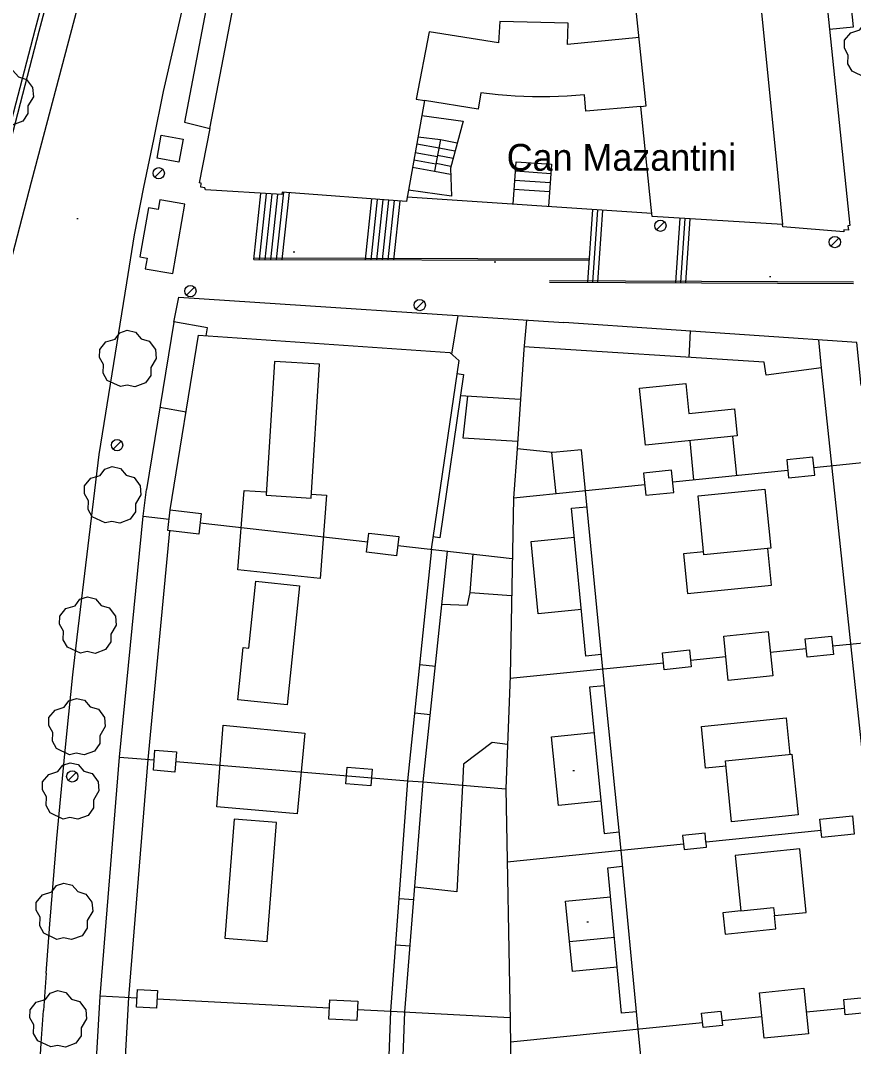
# Model space of a CAD drawing. Extents: x 431390 to 432653, y 4586754 to 4589600.
# Drawn here: x 431776 to 431835, y 4587093.8 to 4587166.5 of the extents above; entities that cross this region are included whole.
import ezdxf

# ---------------------------------------------------------------- set-up
doc = ezdxf.new("R2010")
doc.units = 0
for name, color, linetype in [('COM_16_LN', 7, 'Continuous'), ('COM_17LS_LN', 7, 'Continuous'), ('CON_01_LN', 7, 'Continuous'), ('CON_01FI_LN', 7, 'Continuous'), ('CON_03_LN', 7, 'Continuous'), ('CON_04_LN', 7, 'Continuous'), ('CON_07_LN', 7, 'Continuous'), ('CON_08_LN', 7, 'Continuous'), ('CON_14LN_LN', 7, 'Continuous'), ('CON_14LS_LN', 7, 'Continuous'), ('CON_15_LN', 7, 'Continuous'), ('CON_20_LN', 7, 'Continuous'), ('CON_23_LN', 7, 'Continuous'), ('ENE_06_PT', 7, 'Continuous'), ('ORO_03_PT', 7, 'Continuous'), ('TOP_06_TX', 7, 'Continuous'), ('VEG_03_PT', 7, 'Continuous')]:
    doc.layers.add(name, color=color, linetype=linetype)

msp = doc.modelspace()

# ---------------------------------------------------------------- linework, layer by layer
at = {"layer": 'COM_16_LN'}
msp.add_lwpolyline([(431779.803, 4587175.017), (431778.246, 4587170.313), (431777.035, 4587165.77), (431771.175, 4587143.287), (431765.02, 4587120.517), (431761.564, 4587107.321)], dxfattribs=at)
at = {"layer": 'COM_17LS_LN'}
for points in [[(431795.065, 4587216.598), (431793.497, 4587217.006), (431782.212, 4587174.845), (431780.492, 4587169.028), (431776.775, 4587155.017), (431774.643, 4587146.73), (431773.418, 4587141.925), (431772.51, 4587137.86), (431771.993, 4587135.123), (431771.464, 4587132.387), (431770.958, 4587129.648), (431770.51, 4587126.9), (431770.127, 4587124.069), (431769.799, 4587121.229), (431769.504, 4587118.385), (431769.22, 4587115.54), (431768.925, 4587112.483), (431768.651, 4587109.423), (431768.395, 4587106.362), (431768.15, 4587103.3), (431767.926, 4587100.444), (431767.711, 4587097.587), (431767.513, 4587094.729), (431767.34, 4587091.87)], [(431783.55, 4587147.89), (431784.109, 4587151.289), (431784.768, 4587154.673), (431785.467, 4587158.051), (431786.146, 4587161.432), (431788.285, 4587170.697), (431788.966, 4587173.068), (431792.266, 4587184.632), (431792.939, 4587186.992), (431800.194, 4587215.013), (431798.634, 4587215.414)], [(431780.05, 4587122.825), (431781.595, 4587135.739), (431783.55, 4587147.89)], [(431777.849, 4587099.039), (431778.119, 4587102.51), (431778.614, 4587108.56), (431778.882, 4587111.557), (431779.172, 4587114.563), (431779.453, 4587117.372), (431779.74, 4587120.139), (431780.05, 4587122.825)], [(431777.849, 4587099.039), (431777.652, 4587096.394)], [(431777.554, 4587046.85), (431777.386, 4587049.851), (431777.212, 4587052.828), (431777.056, 4587055.74), (431776.934, 4587058.594), (431776.822, 4587062.83), (431776.77, 4587067.088), (431776.768, 4587071.367), (431776.809, 4587075.663), (431776.88, 4587079.593), (431776.987, 4587083.513), (431777.134, 4587087.422), (431777.325, 4587091.323), (431777.492, 4587094.081), (431777.652, 4587096.394)]]:
    msp.add_lwpolyline(points, dxfattribs=at)
at = {"layer": 'CON_01_LN'}
for points in [[(431833.298, 4587165.852), (431834.732, 4587151.951)], [(431789.431, 4587158.817), (431788.67, 4587154.98)], [(431789.12, 4587154.47), (431789.09, 4587154.61), (431788.79, 4587154.66), (431788.81, 4587154.95), (431788.67, 4587154.98)], [(431803.404, 4587153.958), (431803.349, 4587153.651), (431794.55, 4587154.321), (431794.52, 4587154.14), (431789.12, 4587154.47)], [(431834.732, 4587151.951), (431834.602, 4587151.937), (431834.634, 4587151.629), (431834.325, 4587151.654), (431834.313, 4587151.505), (431830, 4587151.85), (431829.982, 4587152.031), (431820.736, 4587152.597), (431820.715, 4587152.808)], [(431786.89, 4587145.11), (431787.25, 4587146.89), (431814.5, 4587145.08)], [(431786.89, 4587145.11), (431784.94, 4587133.28)], [(431835.534, 4587140.632), (431835.228, 4587143.678), (431814.5, 4587145.08)], [(431784.71, 4587131.38), (431784.94, 4587133.28)], [(431780.668, 4587080.436), (431781.667, 4587097.393), (431783.034, 4587114.323), (431784.71, 4587131.38)]]:
    msp.add_lwpolyline(points, dxfattribs=at)
at = {"layer": 'CON_01FI_LN'}
for points in [[(431789.431, 4587158.817), (431791.586, 4587170.003), (431793.582, 4587180.383)], [(431831.857, 4587179.822), (431833.298, 4587165.852)], [(431820.715, 4587152.808), (431820.672, 4587153.229), (431819.94, 4587160.38), (431816.05, 4587160.04), (431815.95, 4587161.21), (431815.34, 4587161.156), (431814.729, 4587161.113), (431814.118, 4587161.083), (431813.506, 4587161.064), (431812.893, 4587161.057), (431812.281, 4587161.062), (431811.669, 4587161.079), (431811.058, 4587161.108), (431810.447, 4587161.148), (431809.837, 4587161.2), (431809.228, 4587161.264), (431808.62, 4587161.34), (431808.42, 4587160.18), (431804.63, 4587160.8), (431803.492, 4587154.449), (431803.404, 4587153.958)]]:
    msp.add_lwpolyline(points, dxfattribs=at)
at = {"layer": 'CON_03_LN'}
for points in [[(431819.94, 4587160.38), (431820.327, 4587160.414), (431818.925, 4587173.762)], [(431811.852, 4587145.256), (431811.65, 4587143.17), (431811.18, 4587136.14), (431810.92, 4587132.65), (431810.7, 4587120.08), (431810.38, 4587112.09), (431810.7, 4587095.66), (431810.873, 4587081.525)], [(431836.08, 4587135.203), (431832.202, 4587134.809)], [(431830.354, 4587134.622), (431822.198, 4587133.794)], [(431820.219, 4587133.594), (431810.92, 4587132.65)], [(431784.71, 4587131.38), (431786.551, 4587131.169)], [(431788.75, 4587130.917), (431800.619, 4587129.558)], [(431802.734, 4587129.316), (431810.845, 4587128.387)], [(431837.396, 4587122.564), (431833.518, 4587122.175)], [(431825.969, 4587121.416), (431823.468, 4587121.165)], [(431831.653, 4587121.987), (431829.111, 4587121.732)], [(431821.55, 4587120.973), (431810.692, 4587119.882)], [(431783.035, 4587114.334), (431785.495, 4587114.132)], [(431787.026, 4587114.006), (431803.441, 4587112.659), (431804.535, 4587112.57), (431807.314, 4587112.342), (431810.38, 4587112.09)], [(431832.706, 4587109.136), (431824.566, 4587108.317)], [(431822.965, 4587108.156), (431810.481, 4587106.9)], [(431781.669, 4587097.42), (431784.279, 4587097.283)], [(431785.701, 4587097.209), (431797.888, 4587096.573)], [(431799.884, 4587096.468), (431802.257, 4587096.345), (431810.695, 4587095.904)], [(431828.513, 4587095.949), (431825.686, 4587095.665)], [(431834.368, 4587096.538), (431831.662, 4587096.266)], [(431824.311, 4587095.526), (431810.718, 4587094.158)]]:
    msp.add_lwpolyline(points, dxfattribs=at)
at = {"layer": 'CON_04_LN'}
for points in [[(431826.406, 4587187.796), (431826.757, 4587184.3), (431829.653, 4587155.438), (431829.982, 4587152.031)], [(431819.818, 4587165.263), (431814.75, 4587164.76), (431814.79, 4587166.27), (431809.96, 4587166.4), (431809.86, 4587164.89), (431804.95, 4587165.669), (431804.045, 4587160.896), (431804.63, 4587160.8)], [(431806.558, 4587142.844), (431807.002, 4587145.578)], [(431789.183, 4587144.152), (431789.28, 4587144.72), (431786.896, 4587145.138)], [(431786.626, 4587131.826), (431788.64, 4587144.19), (431806.43, 4587142.96), (431807.05, 4587142.4), (431805.1, 4587129.045)], [(431823.374, 4587142.615), (431823.451, 4587144.475)], [(431832.74, 4587141.87), (431832.55, 4587143.859)], [(431836.188, 4587109.486), (431832.74, 4587141.87), (431828.82, 4587141.36), (431828.67, 4587142.27), (431811.67, 4587143.378)], [(431794.012, 4587142.334), (431793.413, 4587132.858), (431796.6, 4587132.656), (431797.199, 4587142.132), (431794.012, 4587142.334)], [(431806.914, 4587141.472), (431807.396, 4587141.402), (431805.709, 4587129.858), (431805.229, 4587129.928)], [(431820.268, 4587136.399), (431819.857, 4587140.45), (431823.119, 4587140.781), (431823.336, 4587138.646), (431826.576, 4587138.975), (431826.77, 4587137.059), (431820.268, 4587136.399)], [(431811.413, 4587139.63), (431807.176, 4587139.895)], [(431811.214, 4587136.655), (431807.36, 4587136.9), (431807.686, 4587139.863)], [(431787.753, 4587138.746), (431785.896, 4587139.082)], [(431823.403, 4587136.717), (431823.684, 4587133.945)], [(431826.435, 4587137.025), (431826.716, 4587134.253)], [(431820.995, 4587082.523), (431819.753, 4587095.067), (431818.546, 4587107.711), (431817.247, 4587120.54), (431815.74, 4587136.08), (431813.71, 4587135.88), (431811.18, 4587136.14)], [(431813.949, 4587132.957), (431813.652, 4587135.886)], [(431832.255, 4587134.285), (431832.126, 4587135.559), (431830.278, 4587135.371), (431830.407, 4587134.097), (431832.255, 4587134.285)], [(431822.273, 4587133.059), (431822.112, 4587134.637), (431820.134, 4587134.436), (431820.294, 4587132.858), (431822.273, 4587133.059)], [(431796.617, 4587132.931), (431797.7, 4587132.87), (431797.24, 4587126.98), (431791.41, 4587127.58), (431791.87, 4587133.2), (431793.429, 4587133.112)], [(431829.14, 4587129.112), (431824.415, 4587128.636), (431823.994, 4587132.82), (431828.719, 4587133.296), (431829.14, 4587129.112)], [(431788.825, 4587131.574), (431788.658, 4587130.117), (431786.459, 4587130.369), (431786.626, 4587131.826), (431788.825, 4587131.574)], [(431817.145, 4587121.588), (431816.06, 4587121.483), (431815.046, 4587131.942), (431816.131, 4587132.047)], [(431786.588, 4587130.354), (431785.048, 4587114.169), (431783.677, 4587097.315), (431782.766, 4587080.929)], [(431800.691, 4587130.18), (431802.806, 4587129.937), (431802.65, 4587128.582), (431800.535, 4587128.825), (431800.691, 4587130.18)], [(431815.742, 4587124.766), (431812.685, 4587124.47), (431812.188, 4587129.599), (431815.244, 4587129.895)], [(431801.663, 4587080.616), (431802.257, 4587096.345), (431803.441, 4587112.659), (431805.155, 4587129.039)], [(431801.711, 4587081.887), (431802.699, 4587081.85), (431803.244, 4587096.293), (431804.535, 4587112.57), (431806.259, 4587128.912)], [(431807.86, 4587125.97), (431808.068, 4587128.705)], [(431824.393, 4587128.855), (431822.966, 4587128.712), (431823.248, 4587125.9), (431829.189, 4587126.496), (431828.929, 4587129.091)], [(431795.786, 4587126.455), (431794.899, 4587118.02), (431791.41, 4587118.387), (431791.8, 4587122.09), (431792.202, 4587122.048), (431792.7, 4587126.78), (431795.786, 4587126.455)], [(431805.863, 4587125.155), (431807.67, 4587125.09), (431807.86, 4587125.97), (431810.799, 4587125.76)], [(431826.136, 4587119.752), (431825.821, 4587122.89), (431828.963, 4587123.206), (431829.278, 4587120.068), (431826.136, 4587119.752)], [(431831.711, 4587121.406), (431831.581, 4587122.701), (431833.446, 4587122.888), (431833.576, 4587121.593), (431831.711, 4587121.406)], [(431821.596, 4587120.512), (431821.475, 4587121.718), (431823.393, 4587121.911), (431823.514, 4587120.705), (431821.596, 4587120.512)], [(431804.302, 4587120.884), (431805.4, 4587120.769)], [(431817.364, 4587119.383), (431816.299, 4587119.275), (431817.347, 4587108.918), (431818.413, 4587109.026)], [(431803.944, 4587117.468), (431805.04, 4587117.353)], [(431825.974, 4587113.685), (431824.53, 4587113.539), (431824.231, 4587116.499), (431830.229, 4587117.106), (431830.49, 4587114.522)], [(431790.37, 4587116.59), (431796.17, 4587116.03), (431795.61, 4587110.31), (431789.93, 4587110.8), (431790.37, 4587116.59)], [(431817.116, 4587111.201), (431814.108, 4587110.897), (431813.616, 4587115.762), (431816.624, 4587116.066)], [(431785.435, 4587113.398), (431785.551, 4587114.819), (431787.083, 4587114.693), (431786.966, 4587113.272), (431785.435, 4587113.398)], [(431810.506, 4587115.224), (431809.43, 4587115.37), (431807.39, 4587113.83), (431807.314, 4587112.342), (431806.93, 4587104.79), (431803.943, 4587105.112)], [(431826.37, 4587109.757), (431825.936, 4587114.064), (431830.641, 4587114.537), (431831.074, 4587110.23), (431826.37, 4587109.757)], [(431799.067, 4587112.443), (431799.163, 4587113.612), (431800.926, 4587113.467), (431800.83, 4587112.298), (431799.067, 4587112.443)], [(431791.149, 4587109.923), (431790.491, 4587101.5), (431793.497, 4587101.265), (431794.155, 4587109.688), (431791.149, 4587109.923)], [(431832.755, 4587108.648), (431832.626, 4587109.934), (431834.925, 4587110.165), (431835.054, 4587108.879), (431832.755, 4587108.648)], [(431824.554, 4587108.316), (431824.49, 4587108.949), (431822.901, 4587108.789), (431823.001, 4587107.793), (431824.603, 4587107.954), (431824.566, 4587108.317), (431824.554, 4587108.316)], [(431831.195, 4587107.83), (431826.622, 4587107.369), (431827.017, 4587103.442), (431829.347, 4587103.677), (431829.404, 4587103.113), (431831.647, 4587103.339), (431831.195, 4587107.83)], [(431819.635, 4587096.301), (431818.585, 4587096.201), (431817.602, 4587106.492), (431818.652, 4587106.603)], [(431802.836, 4587104.32), (431803.875, 4587104.245)], [(431818.274, 4587099.459), (431815.096, 4587099.155), (431814.62, 4587104.14), (431817.798, 4587104.444)], [(431827.017, 4587103.442), (431825.759, 4587103.316), (431825.911, 4587101.802), (431829.5, 4587102.163), (431829.404, 4587103.113)], [(431802.598, 4587101.049), (431803.615, 4587100.975)], [(431818.073, 4587101.559), (431814.895, 4587101.255)], [(431784.245, 4587096.628), (431784.31, 4587097.88), (431785.732, 4587097.806), (431785.667, 4587096.554), (431784.245, 4587096.628)], [(431831.815, 4587094.75), (431828.666, 4587094.433), (431828.342, 4587097.648), (431831.491, 4587097.965), (431831.815, 4587094.75)], [(431799.843, 4587095.676), (431797.847, 4587095.78), (431797.918, 4587097.152), (431799.914, 4587097.048), (431799.843, 4587095.676)], [(431835.877, 4587096.22), (431834.415, 4587096.073), (431834.304, 4587097.171), (431835.766, 4587097.318), (431835.877, 4587096.22)], [(431825.72, 4587095.324), (431824.345, 4587095.186), (431824.241, 4587096.214), (431825.616, 4587096.352), (431825.72, 4587095.324)]]:
    msp.add_lwpolyline(points, dxfattribs=at)
at = {"layer": 'CON_07_LN'}
for points in [[(431786, 4587158.35), (431787.54, 4587158.062), (431787.237, 4587156.442), (431785.697, 4587156.73), (431786, 4587158.35)], [(431785.09, 4587153.197), (431784.49, 4587149.729), (431784.99, 4587149.643), (431784.86, 4587148.89), (431786.819, 4587148.551), (431787.667, 4587153.455), (431785.887, 4587153.763), (431785.769, 4587153.08), (431785.09, 4587153.197)]]:
    msp.add_lwpolyline(points, dxfattribs=at)
at = {"layer": 'CON_08_LN'}
for points in [[(431793.582, 4587180.383), (431791.722, 4587180.721), (431787.646, 4587159.267), (431789.431, 4587158.817)], [(431833.298, 4587165.852), (431834.989, 4587166.026), (431833.55, 4587179.997), (431831.857, 4587179.822)]]:
    msp.add_lwpolyline(points, dxfattribs=at)
at = {"layer": 'CON_14LN_LN'}
msp.add_lwpolyline([(431820.715, 4587152.808), (431803.404, 4587153.958)], dxfattribs=at)
at = {"layer": 'CON_14LS_LN'}
msp.add_lwpolyline([(431783.659, 4587189.377), (431782.477, 4587184.726), (431779.997, 4587174.968), (431778.53, 4587170.215), (431777.325, 4587165.694), (431771.465, 4587143.21), (431765.31, 4587120.44), (431761.854, 4587107.244)], dxfattribs=at)
at = {"layer": 'CON_15_LN'}
for points in [[(431792.555, 4587149.559), (431816.309, 4587149.494)], [(431813.484, 4587147.954), (431834.99, 4587147.859)]]:
    msp.add_lwpolyline(points, dxfattribs=at)
at = {"layer": 'CON_20_LN'}
for points in [[(431792.566, 4587149.659), (431816.316, 4587149.594)], [(431813.484, 4587148.054), (431834.99, 4587147.959)]]:
    msp.add_lwpolyline(points, dxfattribs=at)
at = {"layer": 'CON_23_LN'}
for points in [[(431804.44, 4587159.741), (431807.36, 4587159.35), (431806.46, 4587156.02), (431806.53, 4587154.04), (431803.492, 4587154.449)], [(431804.083, 4587157.745), (431805.66, 4587157.462)], [(431804.17, 4587158.234), (431805.77, 4587158.03), (431805.34, 4587155.8)], [(431805.77, 4587158.03), (431806.942, 4587157.804)], [(431803.971, 4587157.121), (431805.541, 4587156.84)], [(431805.559, 4587156.935), (431806.651, 4587156.725)], [(431805.659, 4587157.454), (431806.789, 4587157.236)], [(431803.878, 4587156.604), (431805.441, 4587156.324)], [(431805.448, 4587156.358), (431806.497, 4587156.156)], [(431810.916, 4587153.459), (431811.12, 4587156.456), (431813.614, 4587156.286), (431813.41, 4587153.293)], [(431803.784, 4587156.079), (431805.34, 4587155.8)], [(431805.34, 4587155.8), (431806.476, 4587155.581)], [(431811.076, 4587155.815), (431813.57, 4587155.645)], [(431811.033, 4587155.174), (431813.526, 4587155.003)], [(431792.555, 4587149.559), (431793.054, 4587154.23)], [(431792.957, 4587149.558), (431793.453, 4587154.205)], [(431793.359, 4587149.557), (431793.853, 4587154.181)], [(431793.762, 4587149.556), (431794.253, 4587154.156)], [(431794.164, 4587149.555), (431794.672, 4587154.312)], [(431794.566, 4587149.553), (431795.071, 4587154.281)], [(431810.989, 4587154.532), (431813.483, 4587154.362)], [(431800.454, 4587149.537), (431800.913, 4587153.837)], [(431800.856, 4587149.536), (431801.312, 4587153.806)], [(431801.258, 4587149.535), (431801.711, 4587153.776)], [(431801.661, 4587149.534), (431802.11, 4587153.746)], [(431802.063, 4587149.533), (431802.509, 4587153.715)], [(431802.465, 4587149.532), (431802.909, 4587153.685)], [(431816.204, 4587147.942), (431816.553, 4587153.085)], [(431816.554, 4587147.94), (431816.902, 4587153.061)], [(431816.905, 4587147.939), (431817.251, 4587153.038)], [(431822.429, 4587147.914), (431822.738, 4587152.474)], [(431822.779, 4587147.913), (431823.088, 4587152.453)], [(431823.13, 4587147.911), (431823.437, 4587152.432)]]:
    msp.add_lwpolyline(points, dxfattribs=at)
at = {"layer": 'ENE_06_PT'}
for p, q in [((431786.102, 4587155.932), (431785.536, 4587155.366)), ((431821.612, 4587152.222), (431821.046, 4587151.656)), ((431833.962, 4587151.062), (431833.396, 4587150.496)), ((431788.342, 4587147.592), (431787.776, 4587147.026)), ((431804.572, 4587146.602), (431804.006, 4587146.036)), ((431783.152, 4587136.692), (431782.586, 4587136.126)), ((431779.982, 4587113.242), (431779.416, 4587112.676))]:
    msp.add_line(p, q, dxfattribs=at)
for centre in [(431785.819, 4587155.649), (431821.329, 4587151.939), (431833.679, 4587150.779), (431788.059, 4587147.309), (431804.289, 4587146.319), (431782.869, 4587136.409), (431779.699, 4587112.959)]:
    msp.add_circle(centre, 0.4, dxfattribs=at)
at = {"layer": 'ORO_03_PT'}
for p, q in [((431816.18, 4587157.34), (431816.28, 4587157.34)), ((431780.01, 4587152.44), (431780.11, 4587152.44)), ((431795.34, 4587150.09), (431795.44, 4587150.09)), ((431809.57, 4587149.39), (431809.67, 4587149.39)), ((431829.05, 4587148.34), (431829.15, 4587148.34)), ((431815.14, 4587113.38), (431815.24, 4587113.38)), ((431816.13, 4587102.66), (431816.23, 4587102.66))]:
    msp.add_line(p, q, dxfattribs=at)
at = {"layer": 'VEG_03_PT'}
for points in [[(431835.824, 4587162.441), (431834.897, 4587162.876), (431834.609, 4587163.397), (431834.632, 4587164.011), (431834.35, 4587164.503), (431834.358, 4587165.066), (431834.799, 4587165.601), (431835.452, 4587165.805), (431835.787, 4587166.256), (431836.313, 4587166.426), (431836.893, 4587166.293), (431837.293, 4587165.827), (431837.867, 4587165.657), (431838.301, 4587165.074), (431838.35, 4587164.432), (431837.967, 4587163.785), (431837.967, 4587163.235), (431837.595, 4587162.701), (431836.856, 4587162.426), (431836.291, 4587162.554), (431835.824, 4587162.441)], [(431774.414, 4587159.081), (431773.487, 4587159.516), (431773.199, 4587160.037), (431773.222, 4587160.651), (431772.94, 4587161.143), (431772.948, 4587161.706), (431773.389, 4587162.241), (431774.042, 4587162.445), (431774.377, 4587162.896), (431774.903, 4587163.066), (431775.483, 4587162.933), (431775.883, 4587162.467), (431776.457, 4587162.297), (431776.891, 4587161.714), (431776.94, 4587161.072), (431776.557, 4587160.425), (431776.557, 4587159.875), (431776.185, 4587159.341), (431775.446, 4587159.066), (431774.881, 4587159.194), (431774.414, 4587159.081)], [(431783.104, 4587140.551), (431782.177, 4587140.986), (431781.889, 4587141.507), (431781.912, 4587142.121), (431781.63, 4587142.613), (431781.638, 4587143.176), (431782.079, 4587143.711), (431782.732, 4587143.915), (431783.067, 4587144.366), (431783.593, 4587144.536), (431784.173, 4587144.403), (431784.573, 4587143.937), (431785.147, 4587143.767), (431785.581, 4587143.184), (431785.63, 4587142.542), (431785.247, 4587141.895), (431785.247, 4587141.345), (431784.875, 4587140.811), (431784.136, 4587140.536), (431783.571, 4587140.664), (431783.104, 4587140.551)], [(431782.034, 4587130.901), (431781.107, 4587131.336), (431780.819, 4587131.857), (431780.842, 4587132.471), (431780.56, 4587132.963), (431780.568, 4587133.526), (431781.009, 4587134.061), (431781.662, 4587134.265), (431781.997, 4587134.716), (431782.523, 4587134.886), (431783.103, 4587134.753), (431783.503, 4587134.287), (431784.077, 4587134.117), (431784.511, 4587133.534), (431784.56, 4587132.892), (431784.177, 4587132.245), (431784.177, 4587131.695), (431783.805, 4587131.161), (431783.066, 4587130.886), (431782.501, 4587131.014), (431782.034, 4587130.901)], [(431780.274, 4587121.681), (431779.347, 4587122.116), (431779.059, 4587122.637), (431779.082, 4587123.251), (431778.8, 4587123.743), (431778.808, 4587124.306), (431779.249, 4587124.841), (431779.902, 4587125.045), (431780.237, 4587125.496), (431780.763, 4587125.666), (431781.343, 4587125.533), (431781.743, 4587125.067), (431782.317, 4587124.897), (431782.751, 4587124.314), (431782.8, 4587123.672), (431782.417, 4587123.025), (431782.417, 4587122.475), (431782.045, 4587121.941), (431781.306, 4587121.666), (431780.741, 4587121.794), (431780.274, 4587121.681)], [(431779.5, 4587114.496), (431778.573, 4587114.931), (431778.285, 4587115.452), (431778.308, 4587116.066), (431778.026, 4587116.558), (431778.034, 4587117.121), (431778.475, 4587117.656), (431779.128, 4587117.86), (431779.463, 4587118.311), (431779.989, 4587118.481), (431780.569, 4587118.348), (431780.969, 4587117.882), (431781.543, 4587117.712), (431781.977, 4587117.129), (431782.026, 4587116.487), (431781.643, 4587115.84), (431781.643, 4587115.29), (431781.271, 4587114.756), (431780.532, 4587114.481), (431779.967, 4587114.609), (431779.5, 4587114.496)], [(431779.054, 4587109.941), (431778.127, 4587110.376), (431777.839, 4587110.897), (431777.862, 4587111.511), (431777.58, 4587112.003), (431777.588, 4587112.566), (431778.029, 4587113.101), (431778.682, 4587113.305), (431779.017, 4587113.756), (431779.543, 4587113.926), (431780.123, 4587113.793), (431780.523, 4587113.327), (431781.097, 4587113.157), (431781.531, 4587112.574), (431781.58, 4587111.932), (431781.197, 4587111.285), (431781.197, 4587110.735), (431780.825, 4587110.201), (431780.086, 4587109.926), (431779.521, 4587110.054), (431779.054, 4587109.941)], [(431778.614, 4587101.421), (431777.687, 4587101.856), (431777.399, 4587102.377), (431777.422, 4587102.991), (431777.14, 4587103.483), (431777.148, 4587104.046), (431777.589, 4587104.581), (431778.242, 4587104.785), (431778.577, 4587105.236), (431779.103, 4587105.406), (431779.683, 4587105.273), (431780.083, 4587104.807), (431780.657, 4587104.637), (431781.091, 4587104.054), (431781.14, 4587103.412), (431780.757, 4587102.765), (431780.757, 4587102.215), (431780.385, 4587101.681), (431779.646, 4587101.406), (431779.081, 4587101.534), (431778.614, 4587101.421)], [(431778.174, 4587093.811), (431777.247, 4587094.246), (431776.959, 4587094.767), (431776.982, 4587095.381), (431776.7, 4587095.873), (431776.708, 4587096.436), (431777.149, 4587096.971), (431777.802, 4587097.175), (431778.137, 4587097.626), (431778.663, 4587097.796), (431779.243, 4587097.663), (431779.643, 4587097.197), (431780.217, 4587097.027), (431780.651, 4587096.444), (431780.7, 4587095.802), (431780.317, 4587095.155), (431780.317, 4587094.605), (431779.945, 4587094.071), (431779.206, 4587093.796), (431778.641, 4587093.924), (431778.174, 4587093.811)]]:
    msp.add_lwpolyline(points, dxfattribs=at)

# ---------------------------------------------------------------- texts
at = {"layer": 'TOP_06_TX'}
msp.add_text('Can Mazantini', height=1.9, dxfattribs=at).set_placement((431810.447, 4587155.829))

doc.saveas('drawing.dxf')
